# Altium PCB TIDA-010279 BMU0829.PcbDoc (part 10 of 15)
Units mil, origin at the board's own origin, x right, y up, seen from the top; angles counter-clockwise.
Board outline 11269.69 x 4438.98 mil, 4 copper layers (Top Layer, Signal Layer 1, Signal Layer 2, Bottom Layer), stack 61.6 mil thick; 1494 components, 725 nets, 3766 pads, 2728 vias.
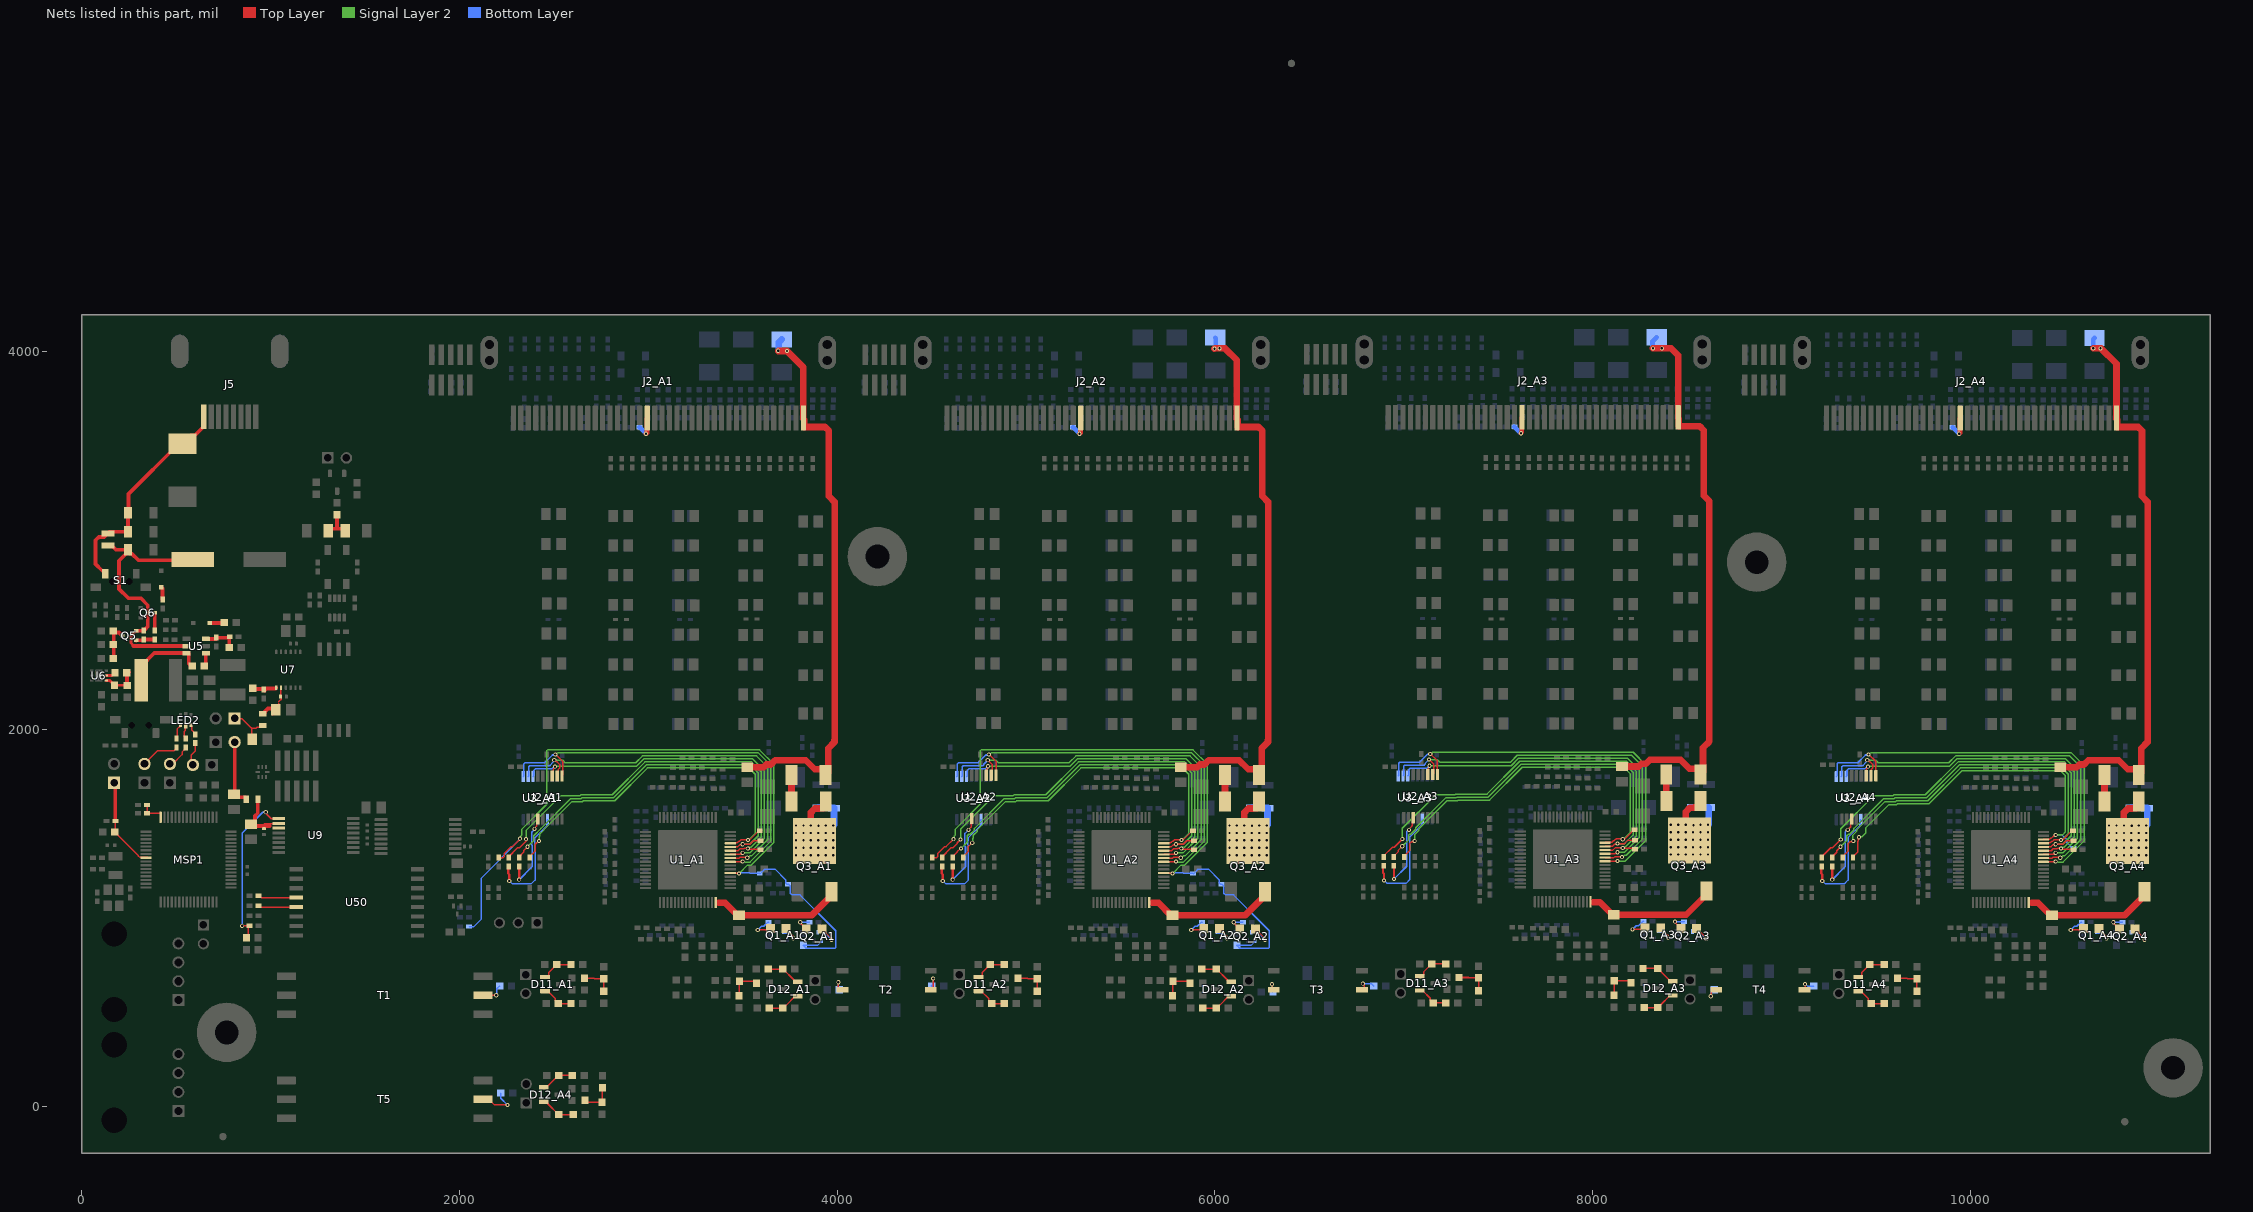
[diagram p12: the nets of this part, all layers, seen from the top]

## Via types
v1: diameter 22.01, hole 12.01, Top Layer to Bottom Layer, tented both sides, 2578 vias
v2: diameter 19.68, hole 7.87, Top Layer to Bottom Layer, tented both sides, 144 vias
v3: diameter 92.52, hole 49.21, Top Layer to Bottom Layer, 4 vias
v4: diameter 19.68, hole 7.87, Top Layer to Bottom Layer, 2 vias

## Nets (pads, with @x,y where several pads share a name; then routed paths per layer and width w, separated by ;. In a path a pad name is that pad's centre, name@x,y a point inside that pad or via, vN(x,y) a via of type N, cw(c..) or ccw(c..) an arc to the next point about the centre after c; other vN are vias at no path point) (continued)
GPIO5_A4: C129_A4.1 R159_A4.1 U1_A4.62 | length 1946.5
  Top Layer w8: R159_A4.1@9377.93,1320.6 9377.93,1324.54 9402.78,1349.39 9402.78,1404.06 9406.75,1408.03 9406.75,1424.48 v1(9409.43,1427.16) ; U1_A4.62@10385.72,1415.22 10387.62,1417.13 10419.02,1417.13 10422.83,1420.94 10426.52,1420.94 10434.95,1429.37 10435.4,1429.37 10445.57,1439.53 v1@10449.36,1439.53
  Signal Layer 2 w8: v1(9409.43,1427.16) 9412.11,1429.84 9425.64,1429.84 9446.66,1450.86 9446.66,1478.64 9568.54,1600.52 9609.83,1600.52 9614.34,1605.04 9780.31,1605.04 9953.72,1778.45 10478.3,1778.45 10502.04,1754.71 10502.04,1454.45 10487.12,1439.53 v1(10451,1439.53)
  Bottom Layer w8: v1(10451,1439.53) 10485.28,1439.53 10510.83,1413.98 10510.83,1399.22 10540.81,1369.24 C129_A4.1@10544.75,1369.24
GPIO6_A1: C133_A1.1 R165_A1.1 U1_A1.61 | length 2002.4
  Top Layer w8: R165_A1.1@2371.08,1320.6 2371.08,1324.54 2400.02,1353.49 2400.02,1392.79 2403.41,1392.79 2418.09,1407.48 v1(2421.26,1407.48) ; U1_A1.61@3433.88,1395.54 3435.78,1397.44 3468.96,1397.44 3472.77,1401.26 3473.76,1401.26 3477.57,1405.07 3481.26,1405.07 3489.68,1413.49 3490.94,1413.49 3492.61,1415.16 3525.45,1415.16 v1(3527.35,1413.26) 3530.03,1415.94 3538.86,1415.94 3585.9,1462.99 C133_A1.1@3589.84,1462.99
  Signal Layer 2 w8: v1(2421.26,1407.48) 2421.58,1407.81 2421.58,1430.48 2425.58,1434.48 2425.58,1444.93 2447.08,1466.43 2447.08,1467.83 2595.64,1616.39 2651.41,1616.39 2655.93,1620.91 2821.89,1620.91 2995.31,1794.32 3533.04,1794.32 3566.07,1761.29 3566.07,1447.87 3541.85,1423.65 3541.53,1423.65 3531.14,1413.26 v1(3527.35,1413.26)
GPIO6_A2: C133_A2.1 R165_A2.1 U1_A2.61 | length 1999.1
  Top Layer w8: R165_A2.1@4666.1,1320.6 4666.1,1324.54 4695.04,1353.49 4695.04,1378.96 4713.71,1397.64 v1(4714.56,1397.64) ; U1_A2.61@5728.89,1395.54 5730.8,1397.44 5763.98,1397.44 5767.79,1401.26 5768.77,1401.26 5772.58,1405.07 5776.27,1405.07 5784.7,1413.49 5785.96,1413.49 5787.63,1415.16 5820.47,1415.16 v1(5822.37,1413.26) 5825.05,1415.94 5833.88,1415.94 5880.92,1462.99 C133_A2.1@5884.86,1462.99
  Signal Layer 2 w8: v1(4714.56,1397.64) 4716.6,1399.68 4716.6,1420.64 4720.6,1424.64 4720.6,1437.46 4742.1,1458.95 4742.1,1467.83 4890.66,1616.39 4946.42,1616.39 4950.94,1620.91 5116.91,1620.91 5290.32,1794.32 5828.05,1794.32 5861.09,1761.29 5861.09,1447.87 5836.87,1423.65 5836.55,1423.65 5826.16,1413.26 v1(5822.37,1413.26)
GPIO6_A3: C133_A3.1 R165_A3.1 U1_A3.61 | length 2006
  Top Layer w8: R165_A3.1@7002.69,1323.81 7002.69,1327.75 7031.64,1356.69 7031.64,1394.72 7041.71,1404.8 7054.39,1404.8 v1(7057.07,1407.48) ; U1_A3.61@8065.49,1398.75 8067.4,1400.65 8100.57,1400.65 8104.38,1404.46 8105.37,1404.46 8109.18,1408.27 8112.87,1408.27 8121.3,1416.7 8122.55,1416.7 8124.22,1418.37 8157.07,1418.37 v1(8158.96,1416.47) 8161.64,1419.15 8170.47,1419.15 8217.52,1466.2 C133_A3.1@8221.45,1466.2
  Signal Layer 2 w8: v1(7057.07,1407.48) 7057.2,1407.6 7057.2,1441.38 7078.69,1462.88 7078.69,1471.04 7227.25,1619.6 7283.02,1619.6 7287.54,1624.12 7453.51,1624.12 7626.92,1797.53 8164.65,1797.53 8197.68,1764.5 8197.68,1451.08 8173.47,1426.86 8173.14,1426.86 8162.75,1416.47 v1(8158.96,1416.47)
GPIO6_A4: C133_A4.1 R165_A4.1 U1_A4.61 | length 2008.4
  Top Layer w8: R165_A4.1@9322.92,1320.6 9322.92,1324.54 9351.87,1353.49 9351.87,1392.79 9363.87,1404.8 9377.22,1404.8 v1(9379.9,1407.48) ; U1_A4.61@10385.72,1395.54 10387.62,1397.44 10420.8,1397.44 10424.61,1401.26 10425.6,1401.26 10429.41,1405.07 10433.1,1405.07 10441.53,1413.49 10442.78,1413.49 10444.45,1415.16 10477.3,1415.16 v1(10479.19,1413.26) 10481.87,1415.94 10490.7,1415.94 10537.75,1462.99 C133_A4.1@10541.68,1462.99
  Signal Layer 2 w8: v1(9379.9,1407.48) 9377.43,1409.95 9377.43,1438.78 9398.92,1460.28 9398.92,1467.83 9547.48,1616.39 9603.25,1616.39 9607.77,1620.91 9773.73,1620.91 9947.15,1794.32 10484.88,1794.32 10517.91,1761.29 10517.91,1447.87 10493.7,1423.65 10493.37,1423.65 10482.98,1413.26 v1(10479.19,1413.26)
GPIO7_A1: C115_A1.2 R149_A1.1 U1_A1.60 | length 2115.9
  Top Layer w8: R149_A1.1@2316.07,1320.6 2316.07,1324.54 2339.76,1348.23 2339.76,1356.41 v1(2360.21,1376.87) ; U1_A1.60@3433.88,1375.85 3435.78,1377.76 3474.51,1377.76 3484.68,1387.93 3496.48,1387.93 v1(3499.16,1390.61) 3499.39,1390.39 3536.83,1390.39 3555.77,1409.33 C115_A1.2@3592.9,1409.33
  Signal Layer 2 w8: v1(2360.21,1376.87) 2393.58,1410.24 2393.58,1435.63 2431.21,1473.25 2431.21,1474.41 2589.06,1632.27 2644.83,1632.27 2649.35,1636.78 2815.32,1636.78 2988.73,1810.2 3539.61,1810.2 3581.95,1767.86 3581.95,1435.5 3536.83,1390.39 3499.39,1390.39 v1(3499.16,1390.61)
GPIO7_A2: C115_A2.2 R149_A2.1 U1_A2.60 | length 2122.3
  Top Layer w8: R149_A2.1@4611.09,1320.6 4611.09,1324.54 4634.78,1348.23 4634.78,1350.64 4652.24,1368.11 v1(4655.5,1368.11) ; U1_A2.60@5728.89,1375.85 5730.8,1377.76 5769.52,1377.76 5779.7,1387.93 5791.5,1387.93 v1(5794.18,1390.61) 5794.4,1390.39 5831.84,1390.39 5850.78,1409.33 C115_A2.2@5887.92,1409.33
  Signal Layer 2 w8: v1(4655.5,1368.11) 4688.6,1401.2 4688.6,1435.63 4696.62,1443.65 4704.35,1443.65 4726.22,1465.53 4726.22,1474.41 4884.08,1632.27 4939.85,1632.27 4944.37,1636.78 5110.33,1636.78 5283.75,1810.2 5834.63,1810.2 5876.96,1767.86 5876.96,1435.5 5831.84,1390.39 5794.4,1390.39 v1(5794.18,1390.61)
GPIO7_A3: C115_A3.2 R149_A3.1 U1_A3.60 | length 2120
  Top Layer w8: R149_A3.1@6947.69,1323.81 6947.69,1327.75 6971.37,1351.44 6971.37,1359.62 v1(6991.82,1380.07) ; U1_A3.60@8065.49,1379.06 8067.4,1380.97 8106.12,1380.97 8116.3,1391.14 8128.09,1391.14 v1(8130.77,1393.82) 8131,1393.59 8168.44,1393.59 8187.38,1412.54 C115_A3.2@8224.52,1412.54
  Signal Layer 2 w8: v1(6991.82,1380.07) 7025.2,1413.45 7025.2,1438.84 7030.01,1443.65 7037.02,1443.65 7062.82,1469.45 7062.82,1477.62 7220.68,1635.48 7276.45,1635.48 7280.96,1639.99 7446.93,1639.99 7620.34,1813.41 8171.22,1813.41 8213.56,1771.07 8213.56,1438.71 8168.44,1393.59 8131,1393.59 v1(8130.77,1393.82)
GPIO7_A4: C115_A4.2 R149_A4.1 U1_A4.60 | length 2119.6
  Top Layer w8: R149_A4.1@9267.92,1320.6 9267.92,1324.54 9291.6,1348.23 9291.6,1356.41 v1(9312.05,1376.87) ; U1_A4.60@10385.72,1375.85 10387.62,1377.76 10426.35,1377.76 10436.53,1387.93 10448.32,1387.93 v1(10451,1390.61) 10451.23,1390.39 10488.67,1390.39 10507.61,1409.33 C115_A4.2@10544.75,1409.33
  Signal Layer 2 w8: v1(9312.05,1376.87) 9345.43,1410.24 9345.43,1435.63 9353.45,1443.65 9359.85,1443.65 9383.05,1466.85 9383.05,1474.41 9540.91,1632.27 9596.68,1632.27 9601.19,1636.78 9767.16,1636.78 9940.57,1810.2 10491.45,1810.2 10533.79,1767.86 10533.79,1435.5 10488.67,1390.39 10451.23,1390.39 v1(10451,1390.61)
GPIO7_R_A1: R149_A1.2 U2_A1.3 | length 434.1
  Top Layer w8: v1(2397.41,1471.81) 2397.41,1475.6 2410.27,1488.46 2410.27,1519.29 U2_A1.3@2415.13,1524.15
  Top Layer w12: v1(2316.07,1202.88) R149_A1.2@2316.07,1273.36
  Bottom Layer w8: v1(2316.07,1202.88) 2384.15,1270.96 2384.15,1385.28 2382.5,1386.93 2382.5,1454.19 2397.41,1469.1 v1(2397.41,1471.81)
GPIO7_R_A2: R149_A2.2 U2_A2.3 | length 438.6
  Top Layer w8: v1(4694.87,1466.53) 4694.87,1467.77 4710.52,1483.42 4710.52,1523.77 U2_A2.3@4710.14,1524.15
  Top Layer w12: v1@4611.09,1200.18 R149_A2.2@4611.09,1273.36
  Bottom Layer w8: v1(4611.09,1202.88) 4679.17,1270.96 4679.17,1376.8 4675.81,1380.16 4675.81,1413.69 4675.81,1447.47 v1(4694.87,1466.53)
GPIO7_R_A3: R149_A3.2 U2_A3.3 | length 436
  Top Layer w8: v1(7027.55,1466.53) 7027.55,1470.32 7041.24,1484.02 7041.24,1485.47 7045.32,1489.55 7045.32,1525.93 U2_A3.3@7046.74,1527.35
  Top Layer w12: v1(6947.69,1206.09) R149_A3.2@6947.69,1276.57
  Bottom Layer w8: v1(6947.69,1206.09) 7015.76,1274.17 7015.76,1457.97 7025.94,1468.14 v1(7027.55,1466.53)
GPIO7_R_A4: R149_A4.2 U2_A4.3 | length 434.3
  Top Layer w8: v1(9350.38,1466.53) 9350.38,1466.9 9366.46,1482.98 9366.46,1523.63 U2_A4.3@9366.97,1524.15
  Top Layer w12: v1(9267.92,1202.88) R149_A4.2@9267.92,1273.36
  Bottom Layer w8: v1(9267.92,1202.88) 9335.99,1270.96 9335.99,1454.76 9347.77,1466.53 v1(9350.38,1466.53)
GPIO8_A1: C135_A1.2 R164_A1.1 U1_A1.59 | length 2219.2
  Top Layer w8: R164_A1.1@2261.06,1320.6 2261.06,1324.54 2307.95,1371.42 2317.92,1371.42 2358.09,1411.59 v1(2352.36,1417.32) ; U1_A1.59@3433.88,1356.17 3475.37,1356.17 3486.93,1367.74 3508.64,1367.74 3508.98,1368.08 3524.27,1368.08 3524.84,1367.51 v1(3526.95,1367.51) 3529.63,1364.83 3588.72,1364.83 C135_A1.2@3592.9,1360.65
  Signal Layer 2 w8: v1(2352.36,1417.32) 2352.36,1463.65 2536.84,1648.14 2638.26,1648.14 2642.78,1652.66 2808.74,1652.66 2982.16,1826.07 3546.19,1826.07 3597.82,1774.44 3597.82,1428.93 3543.4,1374.51 3530.7,1374.51 3526.95,1370.76 v1(3526.95,1367.51)
GPIO8_A2: C135_A2.2 R164_A2.1 U1_A2.59 | length 2214.4
  Top Layer w8: R164_A2.1@4556.08,1320.6 4556.08,1324.54 4602.96,1371.42 4612.93,1371.42 4635.8,1394.29 4635.8,1398.23 v1(4652.93,1415.36) ; U1_A2.59@5728.89,1356.17 5770.38,1356.17 5781.95,1367.74 5803.65,1367.74 5803.99,1368.08 5819.29,1368.08 5819.86,1367.51 v1(5821.97,1367.51) 5824.65,1364.83 5883.74,1364.83 C135_A2.2@5887.92,1360.65
  Signal Layer 2 w8: v1(4652.93,1415.36) 4652.93,1469.21 4831.86,1648.14 4933.27,1648.14 4937.79,1652.66 5103.76,1652.66 5277.17,1826.07 5841.2,1826.07 5892.84,1774.44 5892.84,1428.93 5838.42,1374.51 5825.72,1374.51 5821.97,1370.76 v1(5821.97,1367.51)
GPIO8_A3: C135_A3.2 R164_A3.1 U1_A3.59 | length 2214.4
  Top Layer w8: R164_A3.1@6892.68,1323.81 6892.68,1327.75 6939.56,1374.63 6949.53,1374.63 6992.03,1417.14 v1(6992.03,1417.71) ; U1_A3.59@8065.49,1359.38 8106.98,1359.38 8118.55,1370.94 8140.25,1370.94 8140.59,1371.29 8155.88,1371.29 8156.45,1370.72 v1(8158.56,1370.72) 8161.24,1368.04 8220.33,1368.04 C135_A3.2@8224.52,1363.85
  Signal Layer 2 w8: v1(6992.03,1417.71) 6992.03,1474.93 7168.46,1651.35 7269.87,1651.35 7274.39,1655.87 7440.35,1655.87 7613.77,1829.28 8177.8,1829.28 8229.43,1777.65 8229.43,1432.14 8175.02,1377.72 8162.32,1377.72 8158.56,1373.97 v1(8158.56,1370.72)
GPIO8_A4: C135_A4.2 R164_A4.1 U1_A4.59 | length 2211.2
  Top Layer w8: R164_A4.1@9212.91,1320.6 9212.91,1324.54 9259.79,1371.42 9269.76,1371.42 9313.12,1414.78 v1(9313.12,1415.36) ; U1_A4.59@10385.72,1356.17 10427.21,1356.17 10438.78,1367.74 10460.48,1367.74 10460.82,1368.08 10476.11,1368.08 10476.68,1367.51 v1(10478.79,1367.51) 10481.47,1364.83 10540.56,1364.83 C135_A4.2@10544.75,1360.65
  Signal Layer 2 w8: v1(9313.12,1415.36) 9313.12,1472.57 9488.69,1648.14 9590.1,1648.14 9594.62,1652.66 9760.58,1652.66 9934,1826.07 10498.03,1826.07 10549.66,1774.44 10549.66,1428.93 10495.25,1374.51 10482.55,1374.51 v1@10478.79,1370.76
GPIO8_R_A1: R164_A1.2 U3_A1.3 | length 577.4
  Top Layer w12: R164_A1.2@2261.06,1273.36 2258.46,1270.76 2258.46,1235.79 2263.77,1230.48 v1@2263.77,1200.79 ; v1@2262.42,1194.11 v1(2263.77,1195.47)
  Bottom Layer w8: v1(2263.77,1195.47) 2265.38,1195.47 2280.84,1180.01 2379.46,1180.01 2400.02,1200.57 2400.02,1391.86 2398.38,1393.5 2398.38,1423.82 2464.63,1490.07 2464.63,1518.51 U3_A1.3@2466.31,1520.2
GPIO8_R_A2: R164_A2.2 U3_A2.3 | length 582.2
  Top Layer w12: R164_A2.2@4556.08,1273.36 4553.48,1270.76 4553.48,1235.79 4558.79,1230.48 v1(4558.79,1195.47)
  Bottom Layer w8: v1(4558.79,1195.47) 4560.4,1195.47 4575.86,1180.01 4674.48,1180.01 4695.04,1200.57 4695.04,1383.37 4691.68,1386.73 4691.68,1407.11 4695.04,1410.47 4695.04,1425.47 4759.64,1490.07 4759.64,1518.51 U3_A2.3@4761.33,1520.2
GPIO8_R_A3: R164_A3.2 U3_A3.3 | length 579.4
  Top Layer w12: R164_A3.2@6892.68,1276.57 6890.07,1273.97 6890.07,1239 6895.39,1233.69 v1(6895.39,1198.68)
  Bottom Layer w8: v1(6895.39,1198.68) 6896.99,1198.68 6912.46,1183.21 7011.07,1183.21 7031.64,1203.78 7031.64,1428.67 7096.24,1493.27 7096.24,1521.72 U3_A3.3@7097.92,1523.41
GPIO8_R_A4: R164_A4.2 U3_A4.3 | length 574.1
  Top Layer w12: R164_A4.2@9212.91,1273.36 9210.3,1270.76 9210.3,1235.79 9215.62,1230.48 v1@9215.62,1200.79
  Bottom Layer w8: v1(9215.62,1195.47) 9217.22,1195.47 9232.69,1180.01 9331.3,1180.01 9351.87,1200.57 9351.87,1425.47 9416.47,1490.07 9416.47,1518.51 U3_A4.3@9418.15,1520.2
GPIO9_A1: U1_A1.58 U2_A1.11 U3_A1.11 | length 1930.7
  Top Layer w8: U2_A1.11@2491.9,1752.49 2496.76,1757.35 2496.76,1788.77 2505.36,1797.37 v1(2505.36,1801.16) ; U1_A1.58@3433.88,1336.48 3435.04,1337.65 3488.87,1337.65 3496.08,1344.86 v1@3496.41,1344.86
  Signal Layer 2 w8: v1(2505.36,1801.16) 2507.44,1803.24 2936.87,1803.24 2975.58,1841.95 3552.76,1841.95 3613.69,1781.01 3613.69,1421.9 3536.43,1344.63 3499.39,1344.63 v1(3499.16,1344.86)
  Bottom Layer w8: U3_A1.11@2389.54,1748.54 2394.4,1753.4 2394.4,1781.85 2402.49,1789.94 2490.35,1789.94 2501.57,1801.16 v1(2505.36,1801.16)
GPIO9_A2: U1_A2.58 U2_A2.11 U3_A2.11 | length 1926.4
  Top Layer w8: U2_A2.11@4789.5,1755.85 4791.77,1758.12 4791.77,1788.77 4800.38,1797.37 v1@4800.38,1801.16 ; U1_A2.58@5728.89,1336.48 5730.06,1337.65 5783.88,1337.65 5791.09,1344.86 v1@5791.43,1344.86
  Signal Layer 2 w8: v1(4798.43,1803.12) 4798.55,1803.24 5231.89,1803.24 5270.6,1841.95 5847.78,1841.95 5908.71,1781.01 5908.71,1421.9 5831.44,1344.63 5794.4,1344.63 v1(5794.18,1344.86)
  Bottom Layer w8: U3_A2.11@4684.55,1748.54 4689.41,1753.4 4689.41,1781.85 4697.51,1789.94 4785.37,1789.94 4798.43,1803 v1(4798.43,1803.12)
GPIO9_A3: U1_A3.58 U2_A3.11 U3_A3.11 | length 1925.7
  Top Layer w8: U2_A3.11@7126.95,1759.35 7128.37,1760.77 7128.37,1791.98 7136.98,1800.58 v1@7136.98,1804.37 ; U1_A3.58@8065.49,1339.69 8066.66,1340.86 8120.48,1340.86 8127.69,1348.07 v1@8128.02,1348.07
  Signal Layer 2 w8: v1(7135.3,1806.05) 7135.7,1806.45 7568.49,1806.45 7607.19,1845.15 8184.37,1845.15 8245.31,1784.22 8245.31,1425.11 8168.04,1347.84 8131,1347.84 v1(8130.77,1348.07)
  Bottom Layer w8: U3_A3.11@7021.15,1751.75 7026.01,1756.61 7026.01,1785.06 7034.11,1793.15 7121.97,1793.15 7134.86,1806.05 v1(7135.3,1806.05)
GPIO9_A4: U1_A4.58 U2_A4.11 U3_A4.11 | length 1928.5
  Top Layer w8: U2_A4.11@9448.09,1752.89 9448.6,1753.41 9448.6,1788.77 9457.21,1797.37 v1(9457.21,1801.16) ; U1_A4.58@10385.72,1336.48 10386.89,1337.65 10440.71,1337.65 10447.92,1344.86 v1@10448.25,1344.86
  Signal Layer 2 w8: v1(9457.21,1801.16) 9459.28,1803.24 9888.72,1803.24 9927.42,1841.95 10504.6,1841.95 10565.54,1781.01 10565.54,1421.9 10488.27,1344.63 10451.23,1344.63 v1(10451,1344.86)
  Bottom Layer w8: U3_A4.11@9341.38,1748.54 9346.24,1753.4 9346.24,1781.85 9354.34,1789.95 9442.2,1789.95 9453.42,1801.16 v1(9457.21,1801.16)
GPIO10_A1: U1_A1.57 U2_A1.10 U3_A1.10 | length 2107.2
  Top Layer w8: v1(2501.69,1835.46) 2505.48,1835.46 2512.91,1828.03 2515.09,1828.03 2530.32,1812.8 2530.32,1793.76 2522.35,1785.8 2522.35,1757.35 U2_A1.10@2517.49,1752.49 ; U1_A1.57@3433.88,1316.8 3480.83,1316.8 3485.81,1321.78 v1@3527.32,1321.78
  Signal Layer 2 w8: v1(2501.69,1835.46) 2502.53,1834.62 2546.4,1834.62 2559.41,1821.62 2932.8,1821.62 2969,1857.82 3573.26,1857.82 3631.54,1799.54 3631.54,1414.51 3545.79,1328.76 3537.26,1328.76 3530.08,1321.58 3527.52,1321.58 v1@3527.32,1321.78
  Bottom Layer w8: U3_A1.10@2363.95,1748.54 2367.12,1751.72 2367.12,1800.31 2372.63,1805.82 2477.66,1805.82 2487.69,1815.85 2487.69,1817.68 2501.69,1831.67 v1(2501.69,1835.46)
  other v1: 3523.61,1318.9
GPIO10_A2: U1_A2.57 U2_A2.10 U3_A2.10 | length 2095.9
  Top Layer w8: v1(4796.7,1835.46) 4798.43,1835.46 4821.3,1812.59 4821.3,1793.64 4819.95,1792.29 4819.95,1760.7 U2_A2.10@4815.09,1755.85 ; U1_A2.57@5728.89,1316.8 5775.85,1316.8 5780.83,1321.78 v1@5822.34,1321.78
  Signal Layer 2 w8: v1(4796.7,1835.46) 4797.54,1834.62 4841.42,1834.62 4854.43,1821.62 5227.82,1821.62 5264.02,1857.82 5868.27,1857.82 5926.55,1799.54 5926.55,1414.51 5840.8,1328.76 5832.28,1328.76 5825.1,1321.58 5822.54,1321.58 v1@5822.34,1321.78
  Bottom Layer w8: U3_A2.10@4658.96,1748.54 4662.14,1751.72 4662.14,1800.31 4667.65,1805.82 4770.86,1805.82 4775.55,1810.51 4775.55,1814.31 v1(4796.7,1835.46)
  other v1: 5818.63,1318.9
GPIO10_A3: U1_A3.57 U2_A3.10 U3_A3.10 | length 2095.6
  Top Layer w8: v1(7133.3,1838.67) 7135.03,1838.67 7158.18,1815.53 7158.18,1796.57 7157.4,1795.79 7157.4,1764.21 U2_A3.10@7152.54,1759.35 ; U1_A3.57@8065.49,1320.01 8112.44,1320.01 8117.42,1324.98 v1@8158.93,1324.98
  Signal Layer 2 w8: v1(7133.3,1838.67) 7134.14,1837.83 7178.01,1837.83 7191.02,1824.83 7564.41,1824.83 7600.62,1861.03 8204.87,1861.03 8263.15,1802.75 8263.15,1417.72 8177.4,1331.96 8168.88,1331.96 8161.7,1324.78 8159.13,1324.78 v1@8158.93,1324.98
  Bottom Layer w8: U3_A3.10@6995.56,1751.75 6998.73,1754.93 6998.73,1803.51 7004.25,1809.03 7107.73,1809.03 7112.42,1813.71 7112.42,1817.79 v1(7133.3,1838.67)
  other v1: 8155.23,1322.1
GPIO10_A4: U1_A4.57 U2_A4.10 U3_A4.10 | length 2105
  Top Layer w8: v1(9453.53,1835.46) 9457.32,1835.46 9464.75,1828.03 9466.93,1828.03 9482.16,1812.8 9482.16,1793.76 9474.19,1785.8 9474.19,1753.41 U2_A4.10@9473.68,1752.89 ; U1_A4.57@10385.72,1316.8 10432.67,1316.8 10437.65,1321.78 v1@10479.16,1321.78
  Signal Layer 2 w8: v1(9453.53,1835.46) 9454.37,1834.62 9498.24,1834.62 9511.25,1821.62 9884.64,1821.62 9920.85,1857.82 10525.1,1857.82 10583.38,1799.54 10583.38,1414.51 10497.63,1328.76 10489.11,1328.76 10481.93,1321.58 10479.36,1321.58 v1@10479.16,1321.78
  Bottom Layer w8: U3_A4.10@9315.79,1748.54 9318.96,1751.72 9318.96,1800.31 9324.48,1805.82 9429.51,1805.82 9439.53,1815.85 9439.53,1817.68 9453.53,1831.67 v1(9453.53,1835.46)
  other v1: 10475.46,1318.9
GPIO11_A1: U1_A1.56 U2_A1.9 U3_A1.9 | length 2219.1
  Top Layer w8: v1(2507.8,1865.52) 2509.96,1865.52 2546.19,1829.28 2546.19,1755.6 U2_A1.9@2543.08,1752.49 ; U1_A1.56@3433.88,1297.11 3434.77,1298.01 3494.39,1298.01 v1@3495.29,1298.9
  Signal Layer 2 w8: v1(2507.8,1865.52) 2511.59,1865.52 2519.77,1873.69 3582.62,1873.69 3649.38,1806.93 3649.38,1407.12 3538.28,1296.02 3514.14,1296.02 3513.94,1296.22 3501.84,1296.22 v1(3499.16,1298.9)
  Bottom Layer w8: U3_A1.9@2338.36,1748.54 2341.53,1751.72 2341.53,1816.18 2347.04,1821.69 2450.79,1821.69 2491.93,1862.84 2505.12,1862.84 v1(2507.8,1865.52)
GPIO11_A2: U1_A2.56 U2_A2.9 U3_A2.9 | length 2214.7
  Top Layer w8: v1(4802.82,1865.52) 4804.97,1865.52 4841.21,1829.28 4841.21,1756.37 U2_A2.9@4840.68,1755.85 ; U1_A2.56@5728.89,1297.11 5729.78,1298.01 5789.41,1298.01 v1@5790.3,1298.9
  Signal Layer 2 w8: v1(4802.82,1865.52) 4806.61,1865.52 4814.78,1873.69 5877.63,1873.69 5944.4,1806.93 5944.4,1407.12 5833.3,1296.02 5809.15,1296.02 5808.95,1296.22 5796.86,1296.22 v1(5794.18,1298.9)
  Bottom Layer w8: U3_A2.9@4633.37,1748.54 4636.55,1751.72 4636.55,1816.18 4642.06,1821.69 4745.8,1821.69 4786.95,1862.84 4800.14,1862.84 v1(4802.82,1865.52)
GPIO11_A3: U1_A3.56 U2_A3.9 U3_A3.9 | length 2214.3
  Top Layer w8: v1(7139.41,1868.73) 7141.57,1868.73 7177.8,1832.49 7177.8,1759.67 U2_A3.9@7178.13,1759.35 ; U1_A3.56@8065.49,1300.32 8066.38,1301.21 8126.01,1301.21 v1@8126.9,1302.11
  Signal Layer 2 w8: v1(7139.41,1868.73) 7143.2,1868.73 7151.38,1876.9 8214.23,1876.9 8280.99,1810.14 8280.99,1410.33 8169.89,1299.23 8145.75,1299.23 8145.55,1299.43 8133.45,1299.43 v1(8130.77,1302.11)
  Bottom Layer w8: U3_A3.9@6969.97,1751.75 6973.14,1754.93 6973.14,1819.39 6978.66,1824.9 7082.4,1824.9 7123.54,1866.05 7136.73,1866.05 v1(7139.41,1868.73)
GPIO11_A4: U1_A4.56 U2_A4.9 U3_A4.9 | length 2218
  Top Layer w8: v1(9459.64,1865.52) 9461.8,1865.52 9498.03,1829.28 9498.03,1754.13 U2_A4.9@9499.27,1752.89 ; U1_A4.56@10385.72,1297.11 10386.61,1298.01 10446.24,1298.01 v1@10447.13,1298.9
  Signal Layer 2 w8: v1(9459.64,1865.52) 9463.43,1865.52 9471.61,1873.69 10534.46,1873.69 10601.22,1806.93 10601.22,1407.12 10490.12,1296.02 10465.98,1296.02 10465.78,1296.22 10453.68,1296.22 v1(10451,1298.9)
  Bottom Layer w8: U3_A4.9@9290.2,1748.54 9293.37,1751.72 9293.37,1816.18 9298.89,1821.69 9402.63,1821.69 9443.77,1862.84 9456.96,1862.84 v1(9459.64,1865.52)
LDOIN_A1: C18_A1.2 Q3_A1.3 U1_A1.48 | length 688.7
  Top Layer w35: 3372.55,1080.64 3405.95,1080.64 3473.01,1013.59 3863.76,1013.59 3969.81,1119.64 Q3_A1.3@3969.81,1139.33
LDOIN_A2: C18_A2.2 Q3_A2.3 U1_A2.48 | length 688.7
  Top Layer w35: 5667.57,1080.64 5700.97,1080.64 5768.02,1013.59 6158.77,1013.59 6264.83,1119.64 Q3_A2.3@6264.83,1139.33
LDOIN_A3: C18_A3.2 Q3_A3.3 U1_A3.48 | length 688.7
  Top Layer w35: 8004.16,1083.85 8037.57,1083.85 8104.62,1016.79 8495.37,1016.79 8601.43,1122.85 Q3_A3.3@8601.43,1142.54
LDOIN_A4: C18_A4.2 Q3_A4.3 U1_A4.48 | length 688.7
  Top Layer w35: 10324.39,1080.64 10357.8,1080.64 10424.85,1013.59 10815.6,1013.59 10921.66,1119.64 Q3_A4.3@10921.66,1139.33
LV24V: C179.1 C180.1 D13.2 J5.5 L2.1 S1.3 | length 1192.1
  Top Layer w20: S1.3@124.02,2822.84 124.02,2830.71 116.3,2838.43 108.43,2838.43 73.35,2873.5 73.35,2999.67 90.97,3017.29 118.5,3017.29 146.01,3044.8 C180.1@245.43,3044.8 C179.1@245.43,3145.66 247.39,3147.62 247.39,3245 513.47,3511.08 D13.2@533.47,3511.08 578.47,3556.08 599.76,3556.08 646.04,3602.36 J5.5@646.04,3653.54
LV24VF: C178.1 C181.1 L2.2 Q5.2 R233.2 U5.5 | length 1465.9
  Top Layer w15: 273.23,2439.69 273.23,2443.23 261.2,2455.26 261.2,2493.74 284.07,2516.61 284.07,2519.17 285.83,2520.92 Q5.2@288.39,2520.92
  Top Layer w20: L2.2@147.64,2972.44 158.05,2972.44 181.25,2949.24 C181.1@245.43,2949.24 C181.1@245.43,2939.4 ; 273.23,2439.69 U5.5@554.87,2439.69 U5.5@559.51,2439.69 ; Q5.2@288.39,2520.92 R233.2@328.15,2520.92 ; R233.2@328.74,2521.51 328.74,2525.45 330.55,2527.26 334.49,2527.26 350.1,2542.87 350.1,2655.74 313.54,2692.29 246.91,2692.29 197.01,2742.2 197.01,2891.23 233.52,2927.75 233.78,2927.75 C181.1@245.43,2939.4 ; C178.1@570.65,2893.7 300.97,2893.7 266.93,2927.75 257.08,2927.75 C181.1@245.43,2939.4 ; C178.1@580.24,2903.12 C178.1@599.93,2883.44
MCU_RX: R251.1 U50.13 | length 197.7
  Top Layer w8: R251.1@940.19,1062.99 945.5,1057.68 U50.13@1135.69,1057.68
MCU_TX: R253.2 U50.12 | length 192.2
  Top Layer w8: R253.2@944.88,1111.12 946.79,1109.21 949.94,1109.21 951.47,1107.68 U50.12@1135.69,1107.68
MCU_WAKEIN: D14.2 R220.2 | length 73.4
  Top Layer w20: D14.2@677.42,2561.74 R220.2@750.81,2561.74
ModuleN_A1: J2_A1.30 R140_A1.2 | length 135.1
  Top Layer w25: v1(2988.05,3563.28) 2992.92,3568.15 2992.92,3645.84 J2_A1.30@2994.2,3647.12
  Bottom Layer w25: R140_A1.2@2953.57,3597.76 v1(2988.05,3563.28)
ModuleN_A2: J2_A2.30 R140_A2.2 | length 135.1
  Top Layer w25: v1(5283.07,3563.28) 5287.94,3568.15 5287.94,3645.84 J2_A2.30@5289.22,3647.12
  Bottom Layer w25: R140_A2.2@5248.59,3597.76 v1(5283.07,3563.28)
ModuleN_A3: J2_A3.30 R140_A3.2 | length 135.1
  Top Layer w25: v1(7619.67,3566.49) 7624.53,3571.36 7624.53,3649.05 J2_A3.30@7625.81,3650.33
  Bottom Layer w25: R140_A3.2@7585.18,3600.97 v1(7619.67,3566.49)
ModuleN_A4: J2_A4.30 R140_A4.2 | length 135.1
  Top Layer w25: v1(9939.89,3563.28) 9944.76,3568.15 9944.76,3645.84 J2_A4.30@9946.04,3647.12
  Bottom Layer w25: R140_A4.2@9905.41,3597.76 v1(9939.89,3563.28)
ModuleP_A1: D6_A1.1 J2_A1.20 R36_A1.1 R155_A1.2 | length 3018.6
  Top Layer w35: R36_A1.1@3523.6,1798.86 3611.68,1798.86 3625.1,1812.28 3648.95,1812.28 3671.43,1834.76 3832.99,1834.76 3880.8,1786.95 3924.98,1786.95 3938.98,1772.95 R155_A1.2@3938.98,1756.24 3952.11,1769.37 3952.11,1897.64 3985.88,1931.41 3985.88,1941.06 3986.22,1941.4 3986.22,3202.82 3956.08,3232.95 3956.08,3579.16 3935.58,3599.66 3824.69,3599.66 3824.69,3638.73 3820.97,3642.46 3820.97,3915.26 v1(3734.22,4002.01) 3688.54,4002.01 v1(3687.3,4003.25)
  Bottom Layer w35: v1@3690.94,4005.91 3690.94,4047.75 D6_A1.1@3706.58,4063.39
ModuleP_A2: D6_A2.1 J2_A2.20 R36_A2.1 R155_A2.2 | length 3025.5
  Top Layer w35: R36_A2.1@5818.62,1798.86 5906.69,1798.86 5920.12,1812.28 5943.96,1812.28 5966.44,1834.76 6128,1834.76 6175.81,1786.95 6220,1786.95 6233.99,1772.95 R155_A2.2@6233.99,1756.24 6247.12,1769.37 6247.12,1897.64 6280.9,1931.41 6280.9,1941.06 6281.24,1941.4 6281.24,3202.82 6251.1,3232.95 6251.1,3579.16 6230.6,3599.66 6119.71,3599.66 6119.71,3638.73 6115.99,3642.46 6115.99,3952.91 6053.15,4015.75 v1(6023.62,4015.75) 5998.45,4015.75 v1(5997.08,4014.39)
  Bottom Layer w25: D6_A2.1@6001.28,4072.41 6003.94,4069.76 v1@6003.94,4015.75
ModuleP_A3: D6_A3.1 J2_A3.20 R36_A3.1 R155_A3.2 | length 3061.7
  Top Layer w35: R36_A3.1@8155.22,1802.07 8243.29,1802.07 8256.72,1815.49 8280.56,1815.49 8303.04,1837.97 8464.6,1837.97 8512.41,1790.16 8556.59,1790.16 8570.59,1776.16 R155_A3.2@8570.59,1759.45 8583.72,1772.58 8583.72,1900.85 8617.49,1934.62 8617.49,1944.27 8617.83,1944.61 8617.83,3206.02 8587.7,3236.16 8587.7,3582.37 8567.19,3602.87 8456.31,3602.87 8456.31,3641.94 8452.59,3645.66 8452.59,3978.52 8415.35,4015.75 v1(8366.14,4015.75) v1(8318.56,4015.75)
  Bottom Layer w25: v1@8316.93,4015.75 8316.93,4053.33 D6_A3.1@8338.19,4074.6
ModuleP_A4: D6_A4.1 J2_A4.20 R36_A4.1 R155_A4.2 | length 3018.4
  Top Layer w35: R36_A4.1@10475.45,1798.86 10563.52,1798.86 10576.95,1812.28 10600.79,1812.28 10623.27,1834.76 10784.83,1834.76 10832.64,1786.95 10876.82,1786.95 10890.82,1772.95 R155_A4.2@10890.82,1756.24 10903.95,1769.37 10903.95,1897.64 10937.72,1931.41 10937.72,1941.06 10938.06,1941.4 10938.06,3202.82 10907.93,3232.95 10907.93,3579.16 10887.42,3599.66 10776.54,3599.66 10776.54,3638.73 10772.82,3642.46 10772.82,3933.83 10690.9,4015.75 v1(10649.61,4015.75)
  Bottom Layer w25: v1(10649.61,4015.75) 10649.61,4063.93 D6_A4.1@10656.64,4070.96
  other v1: 10688.98,4015.75
ModuleP_L_A1: C125_A1.2 C191_A1.2 Q3_A1.2 R154_A1.1 | length 443.8
  Top Layer w35: v1(3860.37,1410.98) 3860.57,1410.98 Q3_A1.2@3860.57,1450.35 ; v1(3860.37,1450.35) Q3_A1.2@3860.57,1450.35 ; R154_A1.1@3939.11,1616.25 3939.11,1595.59 3925.11,1581.59 3905.22,1581.59 3903.13,1579.5 3881.48,1579.5 3860.57,1558.6 Q3_A1.2@3860.57,1450.35
  Bottom Layer w35: C125_A1.2@3899.74,1583.22 C191_A1.2@3983.15,1583.22 ; v1@3976.38,1486.22 3983.15,1493 C191_A1.2@3983.15,1581.21
  other v1: 3781.63,1332.24 3821,1332.24 3860.37,1332.24 3899.74,1332.24 3939.11,1332.24 3978.48,1332.24 3781.63,1371.61 3821,1371.61 3860.37,1371.61 3899.74,1371.61 3939.11,1371.61 3978.48,1371.61 3781.63,1410.98 3821,1410.98 3899.74,1410.98 3939.11,1410.98 3978.48,1410.98 3781.63,1450.35 3821,1450.35 3899.74,1450.35 3939.11,1450.35 3978.48,1450.35 3901.53,1487.85 3781.63,1489.72 3821,1489.72 3860.37,1489.72 3939.11,1489.72 3978.48,1489.72
ModuleP_L_A2: C125_A2.2 C191_A2.2 Q3_A2.2 R154_A2.1 | length 443.8
  Top Layer w35: v1(6155.38,1410.98) 6155.59,1410.98 Q3_A2.2@6155.59,1450.35 ; v1(6155.38,1450.35) Q3_A2.2@6155.59,1450.35 ; R154_A2.1@6234.12,1616.25 6234.12,1595.59 6220.13,1581.59 6200.23,1581.59 6198.15,1579.5 6176.49,1579.5 6155.59,1558.6 Q3_A2.2@6155.59,1450.35
  Bottom Layer w35: C125_A2.2@6194.75,1583.22 C191_A2.2@6278.17,1583.22 ; v1@6271.39,1486.22 6278.17,1493 C191_A2.2@6278.17,1581.21
  other v1: 6076.64,1332.24 6116.01,1332.24 6155.38,1332.24 6194.75,1332.24 6234.12,1332.24 6273.49,1332.24 6076.64,1371.61 6116.01,1371.61 6155.38,1371.61 6194.75,1371.61 6234.12,1371.61 6273.49,1371.61 6076.64,1410.98 6116.01,1410.98 6194.75,1410.98 6234.12,1410.98 6273.49,1410.98 6076.64,1450.35 6116.01,1450.35 6194.75,1450.35 6234.12,1450.35 6273.49,1450.35 6196.54,1487.85 6076.64,1489.72 6116.01,1489.72 6155.38,1489.72 6234.12,1489.72 6273.49,1489.72
ModuleP_L_A3: C125_A3.2 C191_A3.2 Q3_A3.2 R154_A3.1 | length 443.8
  Top Layer w35: v1(8491.98,1414.19) 8492.18,1414.19 Q3_A3.2@8492.18,1453.56 ; v1(8491.98,1453.56) Q3_A3.2@8492.18,1453.56 ; R154_A3.1@8570.72,1619.46 8570.72,1598.8 8556.72,1584.8 8536.83,1584.8 8534.74,1582.71 8513.09,1582.71 8492.18,1561.81 Q3_A3.2@8492.18,1453.56
  Bottom Layer w35: C125_A3.2@8531.35,1586.42 C191_A3.2@8614.77,1586.42 ; v1@8607.99,1489.43 8614.77,1496.21 C191_A3.2@8614.77,1584.42
  other v1: 8413.24,1335.45 8452.61,1335.45 8491.98,1335.45 8531.35,1335.45 8570.72,1335.45 8610.09,1335.45 8413.24,1374.82 8452.61,1374.82 8491.98,1374.82 8531.35,1374.82 8570.72,1374.82 8610.09,1374.82 8413.24,1414.19 8452.61,1414.19 8531.35,1414.19 8570.72,1414.19 8610.09,1414.19 8413.24,1453.56 8452.61,1453.56 8531.35,1453.56 8570.72,1453.56 8610.09,1453.56 8533.14,1491.05 8413.24,1492.93 8452.61,1492.93 8491.98,1492.93 8570.72,1492.93 8610.09,1492.93
ModuleP_L_A4: C125_A4.2 C191_A4.2 Q3_A4.2 R154_A4.1 | length 443.8
  Top Layer w35: v1(10812.21,1410.98) 10812.41,1410.98 Q3_A4.2@10812.41,1450.35 ; v1(10812.21,1450.35) Q3_A4.2@10812.41,1450.35 ; R154_A4.1@10890.95,1616.25 10890.95,1595.59 10876.95,1581.59 10857.06,1581.59 10854.97,1579.5 10833.32,1579.5 10812.41,1558.6 Q3_A4.2@10812.41,1450.35
  Bottom Layer w35: C125_A4.2@10851.58,1583.22 C191_A4.2@10935,1583.22 ; v1@10928.22,1486.22 10935,1493 C191_A4.2@10935,1581.21
  other v1: 10733.47,1332.24 10772.84,1332.24 10812.21,1332.24 10851.58,1332.24 10890.95,1332.24 10930.32,1332.24 10733.47,1371.61 10772.84,1371.61 10812.21,1371.61 10851.58,1371.61 10890.95,1371.61 10930.32,1371.61 10733.47,1410.98 10772.84,1410.98 10851.58,1410.98 10890.95,1410.98 10930.32,1410.98 10733.47,1450.35 10772.84,1450.35 10851.58,1450.35 10890.95,1450.35 10930.32,1450.35 10853.37,1487.85 10733.47,1489.72 10772.84,1489.72 10812.21,1489.72 10890.95,1489.72 10930.32,1489.72
NetC147_A1_2: C147_A1.2 R184_A1.1 R188_A1.2 | length 170.6
  Top Layer w8: C147_A1.2@2661.35,681.62 2711.53,681.62 2713.88,679.27 R184_A1.1@2764.06,679.27 R188_A1.2@2764.06,612.34
NetC147_A2_2: C147_A2.2 R184_A2.1 R188_A2.2 | length 170.6
  Top Layer w8: C147_A2.2@4956.37,681.62 5006.54,681.62 5008.9,679.27 R184_A2.1@5059.08,679.27 R188_A2.2@5059.08,612.34
NetC147_A3_2: C147_A3.2 R184_A3.1 R188_A3.2 | length 170.6
  Top Layer w8: C147_A3.2@7292.96,684.83 7343.14,684.83 7345.5,682.48 R184_A3.1@7395.67,682.48 R188_A3.2@7395.67,615.55
NetC147_A4_2: C147_A4.2 R184_A4.1 R188_A4.2 | length 170.6
  Top Layer w8: C147_A4.2@9613.19,681.62 9663.37,681.62 9665.73,679.27 R184_A4.1@9715.9,679.27 R188_A4.2@9715.9,612.34
NetC148_A1_1: C148_A1.1 R185_A1.1 R189_A1.2 | length 172.4
  Top Layer w8: R189_A1.2@3480.39,587.33 3482.42,589.36 R185_A1.1@3482.42,665.2 3561.43,665.2 C148_A1.1@3571.8,654.83
NetC148_A2_1: C148_A2.1 R185_A2.1 R189_A2.2 | length 172.4
  Top Layer w8: R189_A2.2@5775.4,587.33 5777.44,589.36 R185_A2.1@5777.44,665.2 5856.45,665.2 C148_A2.1@5866.81,654.83
NetC148_A3_1: C148_A3.1 R185_A3.1 R189_A3.2 | length 172.4
  Top Layer w8: R189_A3.2@8112,590.53 8114.03,592.57 R185_A3.1@8114.03,668.41 8193.04,668.41 C148_A3.1@8203.41,658.04
NetC148_A4_1: C148_A4.1 R185_A4.1 R189_A4.2 | length 172.4
  Top Layer w8: C148_A4.1@2665.33,34.14 2675.7,23.78 R185_A4.1@2754.71,23.78 2754.71,99.62 R189_A4.2@2756.75,101.65
NetC156_2: C156.2 T1.5 | length 132.8
  Top Layer w8: T1.5@2125,590.55 v1(2194.88,590.55) v1@2192.2,593.23
  Bottom Layer w8: v1(2194.88,590.55) 2196.91,592.58 2196.91,625.06 2211.61,639.76 C156.2@2212.6,639.76 C156.2@2214.57,639.76
NetC157_2: C157.2 T2.2 | length 94.5
  Top Layer w8: v1(4005.91,659.45) 4005.91,631.04 4016.87,620.08 T2.2@4028.05,620.08
  Bottom Layer w8: C157.2@4005.91,620.08 v1(4005.91,659.45)
NetC158_2: C158.2 T2.5 | length 106.6
  Top Layer w8: T2.5@4498.03,620.08 4507.87,629.92 v1(4507.87,679.13)
  Bottom Layer w8: C158.2@4498.03,639.76 4507.87,649.61 v1(4507.87,679.13)
NetC159_2: C159.2 T3.2 | length 77.7
  Top Layer w8: v1(6302.38,649.31) 6302.38,631.04 6299.21,631.04 6310.17,620.08 T3.2@6311.52,620.08
  Bottom Layer w8: C159.2@6302.38,609.94 v1(6302.38,649.31)
NetC160_2: C160.2 T3.5 | length 98.2
  Top Layer w8: T3.5@6779.04,620.08 6780.38,620.08 6791.34,631.04 v1@6791.34,649.61
  Bottom Layer w8: v1(6782.92,652.23) 6828.08,652.23 C160.2@6840.55,639.76
NetC161_2: C161.2 T4.2 | length 92.7
  Top Layer w8: v1(8624.94,585.55) 8626.86,587.47 8626.86,609.12 8637.82,620.08 T4.2@8641.73,620.08
  Bottom Layer w8: v1@8622.05,580.71 8627.62,586.28 8627.62,604 8628.02,604.39 8628.02,605.38 8642.72,620.08 C161.2@8643.7,620.08
NetC162_2: C162.2 T4.5 | length 79.9
  Top Layer w8: T4.5@9121.56,620.08 9124.02,622.54 v1(9124.02,649.61)
  Bottom Layer w8: v1(9124.02,649.61) 9127.76,649.61 9137.61,639.76 C162.2@9169.29,639.76
NetC166_2: C166.2 T5.5 | length 191.1
  Top Layer w8: T5.5@2155.51,49.21 2162.95,49.21 T5.5@2169.19,55.45 ; T5.5@2165.35,29.53 2165.35,29.13 2171.2,23.29 2171.59,23.29 2185.04,9.84 v1(2253.94,9.84)
  Bottom Layer w8: C166.2@2218.43,72.99 2218.43,45.35 v1(2253.94,9.84)
NetC167_1: C167.1 C168.1 J9.1 MSP1.40 | length 497.6
  Top Layer w8: C167.1@177.91,1455.27 C168.1@177.91,1513.33 ; MSP1.40@351.04,1318.82 349.13,1320.72 307.89,1320.72 299.79,1328.82 299.79,1330.02 190.79,1439.02 190.79,1440.01 C167.1@176.09,1454.71 ; C167.1@176.09,1454.71 C167.1@175.11,1454.71 C167.1@176.09,1454.71
  Top Layer w20: J9.1@171.17,1715.6 177.91,1708.86 C168.1@177.91,1513.33
NetC169_1: C169.1 C170.1 MSP1.32 | length 135.6
  Top Layer w8: C169.1@345.94,1598.07 C170.1@345.94,1555.39 416.06,1555.39 417.96,1553.48 MSP1.32@417.96,1533.38
NetC182_2: C182.2 R218.1 R219.2 U5.3 | length 172.2
  Top Layer w20: U5.3@657.24,2477.1 R219.2@711.87,2477.1 ; R219.2@711.87,2483.83 775.27,2483.83 780.76,2478.34 C182.2@780.76,2431.89
NetC185_1: C185.1 J13.1 L5.1 | length 236.8
  Top Layer w8: J13.1@809.36,2056.51 810.7,2055.18 849.16,2055.18 899.49,2004.84 899.49,1949.35 C185.1@902.76,1946.08 ; 899.49,2006.15 900.79,2004.84 922.76,2004.84 926.71,2008.8 948.66,2008.8 L5.1@958.44,2018.58
NetC186_1: C186.1 J12.2 L6.1 | length 357
  Top Layer w20: J12.2@809.8,1931.31 809.8,1654.17 C186.1@807.09,1654.17 821.92,1639.34 866.89,1639.34 870.67,1635.56 L6.1@870.67,1629.66
NetC197_1: C197.1 R237.2 R238.2 U6.1 | length 214.1
  Top Layer w8: R237.2@231.03,2232.06 239.87,2232.06 R237.2@241.27,2230.66
  Top Layer w15: U6.1@129.57,2257.6 148.76,2257.6 C197.1@173.32,2233.05 ; C197.1@173.32,2232.06 R237.2@231.03,2232.06
  Top Layer w20: C197.1@173.32,2232.06 173.32,2232.34 C197.1@173.32,2233.05 ; R237.2@231.03,2235.35 233.67,2237.99 237.91,2237.99 240.27,2240.34 240.27,2297.45 R238.2@239.26,2298.46 248.04,2298.46 250.09,2300.51 R238.2@243.65,2294.07
NetC205_1: C205.1 C206.2 L5.2 U7.2 | length 245.1
  Top Layer w8: C205.1@1027.02,2102.33 C205.1@1043.41,2118.72 ; C205.1@1042.09,2109.52 1042.09,2136.45 ; 1043.41,2145.65 1056.3,2158.55 1055.76,2159.09 1055.76,2168.24 C206.2@1051.89,2172.12 1053.51,2173.74 1053.51,2217.73 U7.2@1055.12,2219.34
  Top Layer w20: L5.2@958.44,2081.57 963.84,2081.57 967.62,2085.35 967.62,2090.75 985.94,2109.07 1020.28,2109.07 C205.1@1027.02,2102.33 1027.02,2096.7 C205.1@1012.02,2081.7
NetC207_1: C207.1 R246.2 U7.1 | length 130.1
  Top Layer w20: R246.2@905.51,2216.54 909.45,2212.6 962.76,2212.6 964.57,2210.79 C207.1@964.57,2208.66 ; C207.1@969.38,2203.85 980.62,2215.09 1008.47,2215.09 1008.55,2215.17 1025.36,2215.17 U7.1@1029.53,2219.34
NetC213_1: C213.1 C214.2 L6.2 U9.2 U9.3 | length 314.8
  Top Layer w8: 967.73,1497.62 969.29,1499.17 1041.5,1499.17 U9.2@1043.31,1500.98
  Top Layer w20: L6.2@931.92,1612.97 931.92,1554.16 917.17,1539.41 917.17,1511.69 902.17,1496.69 C213.1@895.67,1496.69 906.14,1486.22 947.25,1486.22 994.09,1486.22
NetC215_1: C215.1 R247.2 U9.1 | length 858.2
  Top Layer w8: v1(849.53,958.33) 849.64,958.44 890.33,958.44 890.44,958.55 890.22,958.55 882.41,950.74 R247.2@882.41,894.82 ; v1(974.41,1560.21) 977.09,1557.53 977.09,1551.56 1003.88,1524.76 1041.5,1524.76 U9.1@1043.31,1526.57
  Bottom Layer w8: v1(849.53,958.33) 849.65,958.45 849.65,1450.04 958.84,1559.24 973.44,1559.24 v1(974.41,1560.21)
NetC219_1: C219.1 R249.1 R252.2 | length 137.1
  Top Layer w20: R249.1@1323.07,3061.02 1351.61,3061.02 R252.2@1389.01,3061.02 ; 1351.61,3064.96 1351.61,3135.56 C219.1@1351.97,3135.93
NetCBoot1_1: CBoot1.1 U5.1 | length 78.3
  Top Layer w20: CBoot1.1@649.1,2327.31 657.24,2335.45 U5.1@657.24,2402.29
NetCBoot1_2: CBoot1.2 L3.1 U5.6 | length 438.1
  Top Layer w20: L3.1@315.76,2257.6 315.76,2334.37 383.68,2402.29 564.45,2402.29 566.27,2400.48 566.27,2347.73 576.42,2337.57 576.42,2336.01 585.12,2327.31 CBoot1.2@586.11,2327.31
NetD2_A1_1: D2_A1.1 R121_A1.1 | length 144.9
  Top Layer w8: v1(3579.11,936.51) 3639,936.51 D2_A1.1@3645.69,943.19
  Bottom Layer w8: v1(3579.11,936.51) 3598.53,955.93 3610.63,955.93 3633.28,978.59 R121_A1.1@3637.22,978.59
NetD2_A1_2: D2_A1.2 Q1_A1.3 | length 137.3
  Top Layer w8: D2_A1.2@3728.36,943.19 3767,904.55 3767,892.81 v1(3767.56,892.26)
  Bottom Layer w8: Q1_A1.3@3716.01,929.22 3716.01,923.7 3719.49,920.22 3739.59,920.22 v1(3767.56,892.26)
NetD2_A2_1: D2_A2.1 R121_A2.1 | length 144.9
  Top Layer w8: v1(5874.12,936.51) 5934.02,936.51 D2_A2.1@5940.7,943.19
  Bottom Layer w8: v1(5874.12,936.51) 5893.55,955.93 5905.64,955.93 5928.3,978.59 R121_A2.1@5932.24,978.59
NetD2_A2_2: D2_A2.2 Q1_A2.3 | length 137.3
  Top Layer w8: D2_A2.2@6023.38,943.19 6062.02,904.55 6062.02,892.81 v1(6062.58,892.26)
  Bottom Layer w8: Q1_A2.3@6011.03,929.22 6011.03,923.7 6014.51,920.22 6034.61,920.22 v1(6062.58,892.26)
NetD2_A3_1: D2_A3.1 R121_A3.1 | length 144.9
  Top Layer w8: v1(8210.72,939.71) 8270.61,939.71 D2_A3.1@8277.3,946.39
  Bottom Layer w8: v1(8210.72,939.71) 8230.14,959.14 8242.24,959.14 8264.9,981.79 R121_A3.1@8268.83,981.79
NetD2_A3_2: D2_A3.2 Q1_A3.3 | length 137.3
  Top Layer w8: D2_A3.2@8359.98,946.39 8398.62,907.76 8398.62,896.02 v1(8399.17,895.46)
  Bottom Layer w8: Q1_A3.3@8347.62,932.42 8347.62,926.91 8351.1,923.43 8371.21,923.43 v1(8399.17,895.46)
NetD2_A4_1: D2_A4.1 R121_A4.1 | length 144.9
  Top Layer w8: v1(10530.95,936.51) 10590.84,936.51 D2_A4.1@10597.53,943.19
  Bottom Layer w8: v1(10530.95,936.51) 10550.37,955.93 10562.47,955.93 10585.13,978.59 R121_A4.1@10589.06,978.59
NetD2_A4_2: D2_A4.2 Q1_A4.3 | length 137.3
  Top Layer w8: D2_A4.2@10680.21,943.19 10718.85,904.55 10718.85,892.81 v1(10719.4,892.26)
  Bottom Layer w8: Q1_A4.3@10667.85,929.22 10667.85,923.7 10671.33,920.22 10691.44,920.22 v1(10719.4,892.26)
NetD3_A1_1: D3_A1.1 R122_A1.1 | length 96.6
  Top Layer w8: v1(3804.5,977.21) 3807.18,974.53 3807.18,970.58 D3_A1.1@3836.09,941.68
  Bottom Layer w8: v1(3804.5,977.21) 3804.55,977.16 3852.44,977.16 R122_A1.1@3852.49,977.11
NetD3_A1_2: D3_A1.2 Q2_A1.3 | length 167.2
  Top Layer w8: D3_A1.2@3918.77,941.68 3967.13,893.31 3967.13,887.36 v1(3969.81,884.68)
  Bottom Layer w8: Q2_A1.3@3897.24,924.53 3929.97,924.53 v1(3969.81,884.68)
NetD3_A2_1: D3_A2.1 R122_A2.1 | length 96.6
  Top Layer w8: v1(6099.52,977.21) 6102.2,974.53 6102.2,970.58 D3_A2.1@6131.11,941.67
  Bottom Layer w8: v1(6099.52,977.21) 6099.57,977.16 6147.46,977.16 R122_A2.1@6147.51,977.11
NetD3_A2_2: D3_A2.2 Q2_A2.3 | length 167.2
  Top Layer w8: D3_A2.2@6213.78,941.67 6262.15,893.31 6262.15,887.36 v1(6264.83,884.68)
  Bottom Layer w8: Q2_A2.3@6192.26,924.53 6224.98,924.53 v1(6264.83,884.68)
NetD3_A3_1: D3_A3.1 R122_A3.1 | length 96.6
  Top Layer w8: v1(8436.12,980.42) 8438.8,977.74 8438.8,973.79 D3_A3.1@8467.7,944.88
  Bottom Layer w8: v1(8436.12,980.42) 8436.17,980.37 8484.05,980.37 R122_A3.1@8484.1,980.32
NetD3_A3_2: D3_A3.2 Q2_A3.3 | length 167.2
  Top Layer w8: D3_A3.2@8550.38,944.88 8598.75,896.52 8598.75,890.57 v1(8601.43,887.89)
  Bottom Layer w8: Q2_A3.3@8528.86,927.74 8561.58,927.74 v1(8601.43,887.89)
NetD3_A4_1: D3_A4.1 R122_A4.1 | length 96.6
  Top Layer w8: v1(10756.35,977.21) 10759.03,974.53 10759.03,970.58 D3_A4.1@10787.93,941.67
  Bottom Layer w8: v1(10756.35,977.21) 10756.4,977.16 10804.28,977.16 R122_A4.1@10804.33,977.11
NetD3_A4_2: D3_A4.2 Q2_A4.3 | length 167.2
  Top Layer w8: D3_A4.2@10870.61,941.67 10918.98,893.31 10918.98,887.36 v1(10921.66,884.68)
  Bottom Layer w8: Q2_A4.3@10849.09,924.53 10881.81,924.53 v1(10921.66,884.68)
NetD11_A1_1: D11_A1.1 R177_A1.2 R178_A1.1 | length 174
  Top Layer w8: D11_A1.1@2453.16,687.53 2464.93,687.53 2472.74,695.34 2472.74,711.41 2514.7,753.36 R177_A1.2@2515.68,753.36 R178_A1.1@2590.48,753.36
NetD11_A1_2: D11_A1.2 R190_A1.2 R191_A1.1 | length 170.8
  Top Layer w8: D11_A1.2@2453.16,612.72 2466.94,612.72 2507.87,571.79 2507.87,561.37 2522.57,546.67 R190_A1.2@2523.56,546.67 R191_A1.1@2590.48,546.67
NetD11_A2_1: D11_A2.1 R177_A2.2 R178_A2.1 | length 174
  Top Layer w8: D11_A2.1@4748.18,687.53 4759.95,687.53 4767.76,695.34 4767.76,711.41 4809.71,753.36 R177_A2.2@4810.7,753.36 R178_A2.1@4885.5,753.36
NetD11_A2_2: D11_A2.2 R190_A2.2 R191_A2.1 | length 170.8
  Top Layer w8: D11_A2.2@4748.18,612.72 4761.95,612.72 4802.89,571.79 4802.89,561.37 4817.59,546.67 R190_A2.2@4818.57,546.67 R191_A2.1@4885.5,546.67
NetD11_A3_1: D11_A3.1 R177_A3.2 R178_A3.1 | length 174
  Top Layer w8: D11_A3.1@7084.77,690.74 7096.54,690.74 7104.35,698.55 7104.35,714.62 7146.31,756.57 R177_A3.2@7147.29,756.57 R178_A3.1@7222.1,756.57
NetD11_A3_2: D11_A3.2 R190_A3.2 R191_A3.1 | length 170.8
  Top Layer w8: D11_A3.2@7084.77,615.93 7098.55,615.93 7139.48,575 7139.48,564.58 7154.18,549.88 R190_A3.2@7155.17,549.88 R191_A3.1@7222.1,549.88
NetD11_A4_1: D11_A4.1 R177_A4.2 R178_A4.1 | length 174
  Top Layer w8: D11_A4.1@9405,687.53 9416.77,687.53 9424.58,695.34 9424.58,711.41 9466.54,753.36 R177_A4.2@9467.52,753.36 R178_A4.1@9542.33,753.36
NetD11_A4_2: D11_A4.2 R190_A4.2 R191_A4.1 | length 170.8
  Top Layer w8: D11_A4.2@9405,612.72 9418.78,612.72 9459.71,571.79 9459.71,561.37 9474.41,546.67 R190_A4.2@9475.4,546.67 R191_A4.1@9542.33,546.67
NetD12_A1_1: D12_A1.1 R194_A1.2 R195_A1.1 | length 177.6
  Top Layer w8: R194_A1.2@3640.36,522.34 R195_A1.1@3711.77,522.34 3726.47,537.04 3728.43,537.04 3777.72,586.33 D12_A1.1@3791.5,586.33
NetD12_A1_2: D12_A1.2 R181_A1.2 R182_A1.1 | length 187.3
  Top Layer w8: R181_A1.2@3634.53,729.57 R182_A1.1@3711.77,729.57 3712.75,729.57 3769.91,672.42 3769.91,668.95 3777.72,661.13 D12_A1.2@3791.5,661.13
NetD12_A2_1: D12_A2.1 R194_A2.2 R195_A2.1 | length 177.6
  Top Layer w8: R194_A2.2@5935.38,522.34 R195_A2.1@6006.78,522.34 6021.48,537.04 6023.44,537.04 6072.73,586.33 D12_A2.1@6086.51,586.33
NetD12_A2_2: D12_A2.2 R181_A2.2 R182_A2.1 | length 187.3
  Top Layer w8: R181_A2.2@5929.54,729.57 R182_A2.1@6006.78,729.57 6007.77,729.57 6064.92,672.42 6064.92,668.95 6072.73,661.13 D12_A2.2@6086.51,661.13
NetD12_A3_1: D12_A3.1 R194_A3.2 R195_A3.1 | length 177.6
  Top Layer w8: R194_A3.2@8271.97,525.55 R195_A3.1@8343.38,525.55 8358.08,540.25 8360.04,540.25 8409.33,589.54 D12_A3.1@8423.11,589.54
NetD12_A3_2: D12_A3.2 R181_A3.2 R182_A3.1 | length 187.3
  Top Layer w8: R181_A3.2@8266.14,732.78 R182_A3.1@8343.38,732.78 8344.36,732.78 8401.52,675.62 8401.52,672.15 8409.33,664.34 D12_A3.2@8423.11,664.34
NetD12_A4_1: D12_A4.1 R194_A4.2 R195_A4.1 | length 177.6
  Top Layer w8: D12_A4.1@2445.64,102.65 2459.42,102.65 2508.71,151.94 2510.67,151.94 R195_A4.1@2525.37,166.64 R194_A4.2@2596.77,166.64
NetD12_A4_2: D12_A4.2 R181_A4.2 R182_A4.1 | length 187.3
  Top Layer w8: D12_A4.2@2445.64,27.84 2459.42,27.84 2467.23,20.03 2467.23,16.56 2524.38,-40.59 R182_A4.1@2525.37,-40.59 R181_A4.2@2602.61,-40.59
NetD15_1: D15.1 R240.1 | length 69.1
  Top Layer w20: D15.1@421.01,2751.22 428.12,2744.12 R240.1@428.12,2685.04
NetJ17_2: J17.2 R226.1 | length 126.5
  Top Layer w8: J17.2@588.73,1810.3 580.54,1818.49 580.54,1862.61 600.39,1882.46 R226.1@600.39,1925.2
NetJ18_2: J18.2 R227.1 | length 155
  Top Layer w8: J18.2@455.99,1805.16 461.58,1810.75 J18.2@461.58,1812.68 ; J18.2@467.18,1815.6 481.76,1815.6 531.41,1865.25 531.41,1878.55 550.99,1898.14 R227.1@550.99,1902.07 ; J18.2@467.18,1820.72 J18.2@478.08,1831.62
NetJ20_2: J20.2 R228.1 | length 194.3
  Top Layer w8: J20.2@339.57,1823.71 400.36,1884.5 486.87,1884.5 493.27,1890.91 494.09,1890.91 501.97,1898.78 R228.1@501.97,1899.61
NetLED2_4: LED2.4 R226.2 | length 57.9
  Top Layer w8: LED2.4@579.72,2020.67 578.42,2019.36 578.42,2017.48 582.12,2013.78 582.12,1994.66 600.39,1976.38 R226.2@600.39,1972.44
NetLED2_5: LED2.5 R227.2 | length 74.2
  Top Layer w8: R227.2@550.99,1949.32 544.03,1956.28 544.03,1987.94 548.03,1991.94 548.03,2014.57 LED2.5@551.18,2017.72
NetLED2_6: LED2.6 R228.2 | length 87.7
  Top Layer w8: R228.2@501.9,1949.9 505.2,1946.6 506.57,1947.97 506.57,2002.72 514.5,2010.66 517.46,2010.66 518.76,2011.96 518.76,2016.8 LED2.6@522.64,2020.67
NetQ5_1: Q5.1 R233.1 R234.1 | length 102.1
  Top Layer w20: Q5.1@288.39,2469.74 289.13,2470.49 326.93,2470.49 328.74,2472.3 R233.1@328.74,2474.27 R234.1@387.5,2474.27
NetQ5_3: Q5.3 R230.1 R231.1 R232.1 | length 187.5
  Top Layer w20: R231.1@165.57,2518.64 R231.1@166.47,2519.54 ; R232.1@169.42,2370.08 R231.1@169.42,2511.44 ; R231.1@175.17,2510.84 197.01,2510.84 212.52,2495.33 Q5.3@213.58,2495.33
NetQ6_3: Q6.3 R234.2 | length 94.2
  Top Layer w20: Q6.3@387.07,2615.55 387.28,2615.34 387.28,2521.72 R234.2@387.5,2521.51
NetR154_A1_2: R154_A1.2 R155_A1.1 | length 140
  Top Layer w35: R155_A1.1@3757.87,1756.24 R155_A1.1@3757.87,1756.24 3757.94,1616.32 R154_A1.2@3758,1616.25
NetR154_A2_2: R154_A2.2 R155_A2.1 | length 140
  Top Layer w35: R155_A2.1@6052.89,1756.24 6052.95,1756.17 R154_A2.2@6053.02,1616.25 R154_A2.2@6053.02,1616.25
NetR154_A3_2: R154_A3.2 R155_A3.1 | length 140
  Top Layer w35: R155_A3.1@8389.49,1759.45 8389.55,1759.38 R154_A3.2@8389.62,1619.46 R154_A3.2@8389.62,1619.46
NetR154_A4_2: R154_A4.2 R155_A4.1 | length 140
  Top Layer w35: R155_A4.1@10709.72,1756.24 10709.78,1756.17 R154_A4.2@10709.85,1616.25 R154_A4.2@10709.85,1616.25
NetR238_1: R238.1 U6.2 | length 53
  Top Layer w15: U6.2@129.57,2283.19 160.02,2283.19 175.29,2298.46 R238.1@176.27,2298.46
NFAULT/GPIO2_A1: C114_A1.1 Q2_A1.1 R137_A1.2 R150_A1.1 R210.1 R215_A1.1 U1_A1.53 | length 4306.9
  Top Layer w8: R150_A1.1@2207.17,1319.29 2230.98,1319.29 2237.38,1325.68 2237.38,1341.27 2273.89,1377.78 2282.49,1377.78 2321.11,1416.41 v1(2321.11,1419.84) ; U1_A1.53@3433.88,1238.06 3434.96,1236.97 3479.5,1236.97 v1(3480.58,1235.89)
  Signal Layer 2 w8: v1(2321.11,1419.84) 2323.67,1422.4 2323.67,1432.31 2330.52,1439.16 2330.52,1470.84 2461.7,1602.02 2461.7,1884.88 2466.39,1889.57 3589.19,1889.57 3665.25,1813.51 3665.25,1400.54 3544.85,1280.14 3525.36,1280.14 3481.11,1235.89 v1(3480.58,1235.89)
  Bottom Layer w8: R210.1@2051.18,954.72 2076.77,954.72 2116.14,994.09 2116.14,1211.44 2321.11,1416.41 v1(2321.11,1419.84) ; v1(3480.58,1235.89) 3484.37,1235.89 3488.64,1240.16 3534.8,1240.16 3539.07,1235.89 3589.32,1235.89 C114_A1.1@3589.84,1235.37 3593.78,1235.37 3609.46,1251.05 3609.46,1252.09 3616.42,1259.05 3670.17,1259.05 3727.88,1201.34 3727.88,1185.62 3735.7,1177.81 3743.57,1177.81 3751.38,1170 3751.38,1130.99 3760.41,1121.96 3803.31,1121.96 3992.69,932.59 3992.69,843.25 3988.01,838.57 3837.23,838.57 3836.68,839.12 3835.7,839.12 3821,853.82 R137_A1.2@3821,854.81 3822.94,856.75 3897.97,856.75 3917.32,876.1 Q2_A1.1@3917.32,881.62
NFAULT/GPIO2_A2: C114_A2.1 Q2_A2.1 R137_A2.2 R150_A2.1 R215_A2.1 U1_A2.53 | length 3714.4
  Top Layer w8: R150_A2.1@4502.19,1319.29 4526,1319.29 4532.4,1325.68 4532.4,1341.27 4568.91,1377.78 4576.01,1377.78 4615.54,1417.32 v1(4616.13,1417.32) ; U1_A2.53@5728.89,1238.06 5729.98,1236.97 5774.51,1236.97 v1(5775.6,1235.89)
  Signal Layer 2 w8: v1(4616.13,1417.32) 4618.69,1419.88 4618.69,1432.31 4625.54,1439.16 4625.54,1470.84 4756.72,1602.02 4756.72,1884.88 4761.4,1889.57 5884.21,1889.57 5960.27,1813.51 5960.27,1400.54 5839.87,1280.14 5820.38,1280.14 5776.12,1235.89 v1(5775.6,1235.89)
  Bottom Layer w8: v1(5775.6,1235.89) 5779.39,1235.89 5783.66,1240.16 5829.82,1240.16 5834.09,1235.89 5884.33,1235.89 C114_A2.1@5884.86,1235.37 5888.79,1235.37 5904.48,1251.05 5904.48,1252.09 5911.43,1259.05 5965.19,1259.05 6022.9,1201.34 6022.9,1185.62 6030.71,1177.81 6038.59,1177.81 6046.4,1170 6046.4,1130.99 6055.42,1121.96 6098.33,1121.96 6287.71,932.59 6287.71,843.25 6283.02,838.57 6132.25,838.57 6131.7,839.12 6130.71,839.12 6116.01,853.82 R137_A2.2@6116.01,854.81 6117.95,856.75 6192.98,856.75 6212.34,876.1 Q2_A2.1@6212.34,881.62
